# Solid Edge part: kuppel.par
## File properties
Author: Administrator
Template: Normal.par
Last saved by: Administrator
Revision: 2
Application: Solid Edge
Accuracy: 0,990
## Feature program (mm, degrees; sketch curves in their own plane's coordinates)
sketch for "unnamed RevolvedProtrusion 1" plane through (0, 0, 0) normal (0, -1, 0) x-axis (1, 0, 0)
revolve "unnamed RevolvedProtrusion 1" add finite 360 deg
sketch for "unnamed RevolvedProtrusion 2" plane through (0, 0, 0) normal (0, -1, 0) x-axis (1, 0, 0)
revolve "unnamed RevolvedProtrusion 2" add finite 360 deg
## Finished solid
Body 1: solid body, 13 faces, 12 edges, 0 vertices.
  Faces by surface: plane 6, cylinder 4, torus 2, cone 1
  Edges by curve: circle 12
Bounding box of the edges (mm; curved faces can reach further): 42.995 x 42.995 x 10.000, from (-21.4977, -21.4977, -1) to (21.4977, 21.4977, 9).
Cylindrical faces by radius (mm): R16.5 x1, R17.5 x1, R19 x1, R20 x1
Conical faces (half-angle, radius in mm at the cone's reference point): 44.9554 deg R21.4977 x1
Toroidal faces (ring radius, tube radius in mm): R11.5 r5 x1, R11.5 r6 x1
Planar faces by outward normal: +z 2, -z 4
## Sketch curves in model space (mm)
line (0, 0, 5.6331) -> (0, 0, 0.5346)
line (-20, 0, 1.5) -> (-17.5, 0, 1.5)
line (-17.5, 0, 1.5) -> (-17.5, 0, 3)
arc centre (-11.5, 0, 3) radius 6 from (-17.5, 0, 3) through (-15.6174, 0, 7.3642) to (-11.5, 0, 9)
line (-11.5, 0, 9) -> (0, 0, 9)
line (0, 0, 8) -> (0, 0, 9)
line (-11.5, 0, 8) -> (0, 0, 8)
arc centre (-11.5, 0, 3) radius 5 from (-16.5, 0, 3) through (-14.9312, 0, 6.6369) to (-11.5, 0, 8)
line (-16.5, 0, 0.5) -> (-16.5, 0, 3)
line (-19, 0, 0.5) -> (-16.5, 0, 0.5)
line (-19, 0, -1) -> (-19, 0, 0.5)
line (-19, 0, -1) -> (-20, 0, -1)
line (-20, 0, -1) -> (-20, 0, 1.5)
line (-21.4977, 0, 0) -> (-20, 0, 1.5)
line (-20, 0, 1.5) -> (-19.9977, 0, 0)
line (-19.9977, 0, 0) -> (-21.4977, 0, 0)
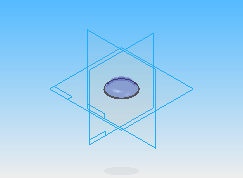
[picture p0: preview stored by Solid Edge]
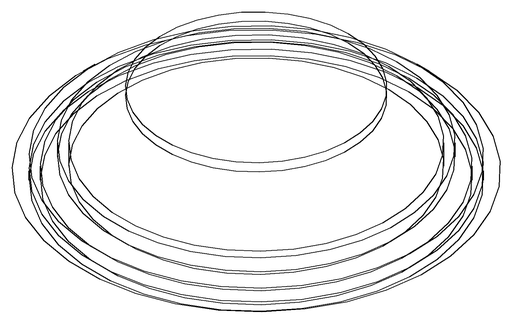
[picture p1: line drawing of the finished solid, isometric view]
